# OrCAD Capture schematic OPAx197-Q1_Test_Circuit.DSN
size A; title: OPAx197-Q1 36-V, Precision, Rail-to-Rail Input/Output, Low-Off; rev: 1.3; note: Datasheet: SBOS918A  EVM: N/A
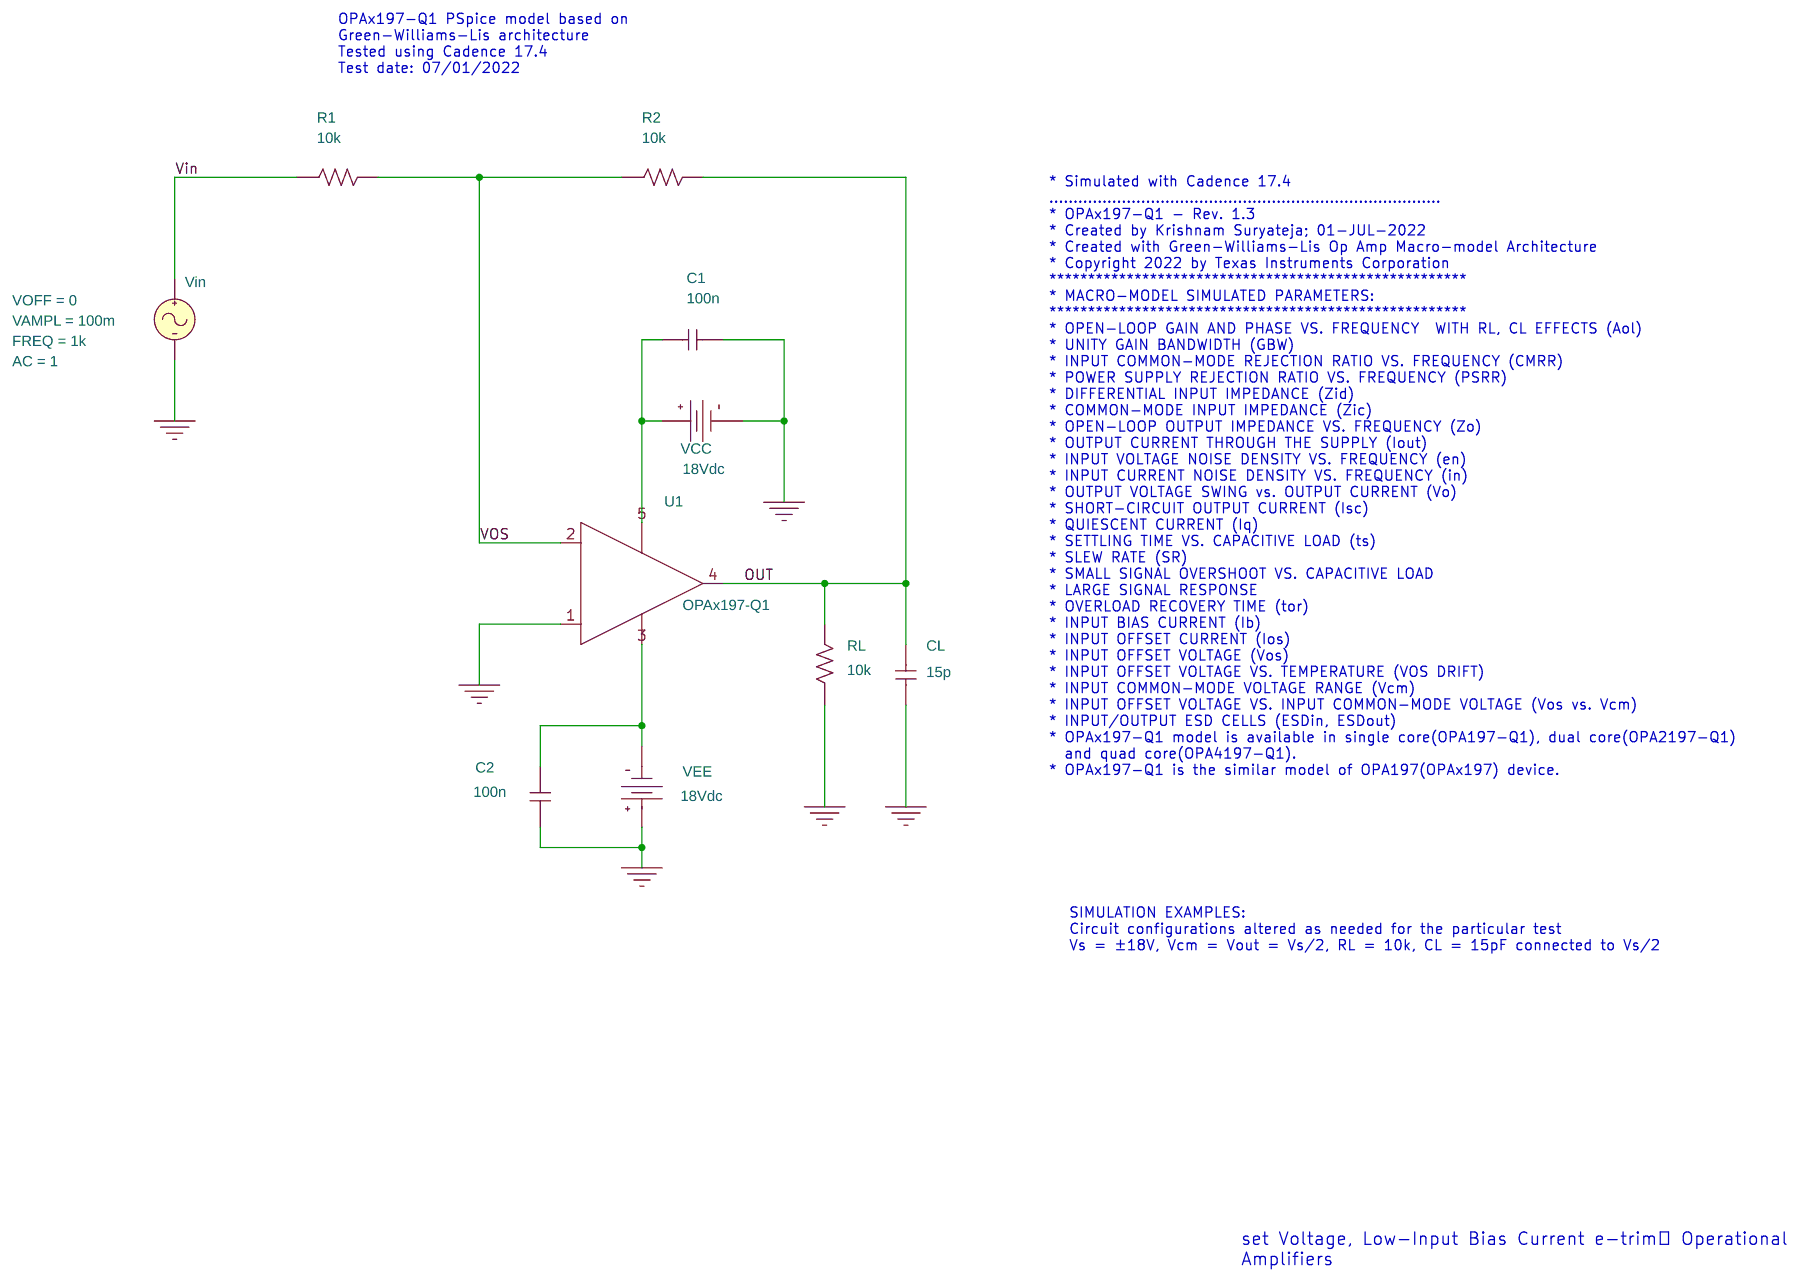
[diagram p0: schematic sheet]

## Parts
C1  100n  [cap196]
C2  100n  [cap196]
CL  15p  [cap196]
R1  10k  [AXRC05]
R2  10k  [AXRC05]
RL  10k  [AXRC05]
U1  OPAx197-Q1
VCC  VDC
VEE  VDC
Vin  VSIN

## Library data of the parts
C1 C2 CL = C
R1 R2 RL = R
U1 = OPAx197-Q1
VCC VEE = VDC: DC: 18Vdc
Vin = VSIN: AC: 1; FREQ: 1k; VAMPL: 100m; VOFF: 0

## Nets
Vin: R1.1 Vin.1(+)
0: C1.2 C2.1 CL.2 RL.1 U1.1(+) VCC.1(-) VEE.0(+) Vin.2(-)
OUT: CL.1 R2.2 RL.2 U1.4(OUT)
VOS: R1.2 R2.1 U1.2(-)
N27303: C1.1 U1.5(V+) VCC.0(+)
N27354: C2.2 U1.3(V-) VEE.1(-)

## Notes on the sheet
- OPAx197-Q1 PSpice model based on
  Green-Williams-Lis architecture
  Tested using Cadence 17.4
  Test date: 07/01/2022
- * Simulated with Cadence 17.4
  .................................................................................
  * OPAx197-Q1 - Rev. 1.3
  * Created by Krishnam Suryateja; 01-JUL-2022
  * Created with Green-Williams-Lis Op Amp Macro-model Architecture
  * Copyright 2022 by Texas Instruments Corporation
  ******************************************************
  * MACRO-MODEL SIMULATED PARAMETERS:
  ******************************************************
  * OPEN-LOOP GAIN AND PHASE VS. FREQUENCY  WITH RL, CL EFFECTS (Aol)
  * UNITY GAIN BANDWIDTH (GBW)
  * INPUT COMMON-MODE REJECTION RATIO VS. FREQUENCY (CMRR)
  * POWER SUPPLY REJECTION RATIO VS. FREQUENCY (PSRR)
  * DIFFERENTIAL INPUT IMPEDANCE (Zid)
  * COMMON-MODE INPUT IMPEDANCE (Zic)
  * OPEN-LOOP OUTPUT IMPEDANCE VS. FREQUENCY (Zo)
  * OUTPUT CURRENT THROUGH THE SUPPLY (Iout)
  * INPUT VOLTAGE NOISE DENSITY VS. FREQUENCY (en)
  * INPUT CURRENT NOISE DENSITY VS. FREQUENCY (in)
  * OUTPUT VOLTAGE SWING vs. OUTPUT CURRENT (Vo)
  * SHORT-CIRCUIT OUTPUT CURRENT (Isc)
  * QUIESCENT CURRENT (Iq)
  * SETTLING TIME VS. CAPACITIVE LOAD (ts)
  * SLEW RATE (SR)
  * SMALL SIGNAL OVERSHOOT VS. CAPACITIVE LOAD
  * LARGE SIGNAL RESPONSE
  * OVERLOAD RECOVERY TIME (tor)
  * INPUT BIAS CURRENT (Ib)
  * INPUT OFFSET CURRENT (Ios)
  * INPUT OFFSET VOLTAGE (Vos)
  * INPUT OFFSET VOLTAGE VS. TEMPERATURE (VOS DRIFT)
  * INPUT COMMON-MODE VOLTAGE RANGE (Vcm)
  * INPUT OFFSET VOLTAGE VS. INPUT COMMON-MODE VOLTAGE (Vos vs. Vcm)
  * INPUT/OUTPUT ESD CELLS (ESDin, ESDout)
  * OPAx197-Q1 model is available in single core(OPA197-Q1), dual core(OPA2197-Q1)
    and quad core(OPA4197-Q1).
  * OPAx197-Q1 is the similar model of OPA197(OPAx197) device.
- SIMULATION EXAMPLES:
  Circuit configurations altered as needed for the particular test
  Vs = ±18V, Vcm = Vout = Vs/2, RL = 10k, CL = 15pF connected to Vs/2
- set Voltage, Low-Input Bias Current e-trim™ Operational
- Amplifiers
